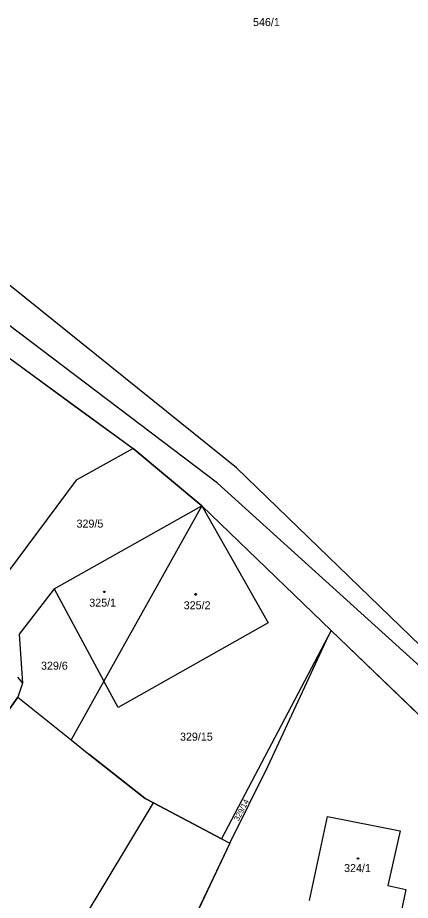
# Model space of a CAD drawing. Extents: x -634640 to -629202, y -1196156 to -1190068.
# Drawn here: x -632304.1 to -632220.7, y -1192469.9 to -1192282.4 of the extents above; entities that cross this region are included whole.
import ezdxf

# ---------------------------------------------------------------- set-up
doc = ezdxf.new("R2010")
doc.units = 0
for name, color, linetype in [('Obvod převzatý', 7, 'Continuous'), ('Obvod šetřený', 7, 'Continuous'), ('Vrstva 1', 7, 'Continuous'), ('Vrstva 2', 7, 'Continuous'), ('Vrstva 5', 7, 'Continuous')]:
    doc.layers.add(name, color=color, linetype=linetype)

msp = doc.modelspace()

# ---------------------------------------------------------------- linework, layer by layer
at = {"layer": 'Obvod převzatý'}
for points in [[(-632163.67, -1192480.89), (-632170.84, -1192475.395), (-632178.01, -1192469.9), (-632207.785, -1192441.235), (-632237.56, -1192412.57), (-632251.305, -1192399.34), (-632265.05, -1192386.11), (-632272.32, -1192380.04), (-632279.59, -1192373.97)], [(-632304.09, -1192426.76), (-632292.79, -1192435.85), (-632289.05, -1192438.85)], [(-632260.85, -1192456.84), (-632268.06, -1192453.015), (-632275.27, -1192449.19), (-632277.03, -1192448.26), (-632283.04, -1192443.555), (-632289.05, -1192438.85)], [(-632260.85, -1192456.84), (-632259.09, -1192457.78), (-632267.47, -1192475.48), (-632270.585, -1192482.88), (-632273.7, -1192490.28), (-632274.595, -1192496.04), (-632275.49, -1192501.8)]]:
    msp.add_lwpolyline(points, dxfattribs=at)
at = {"layer": 'Obvod šetřený'}
for points in [[(-632350.27, -1192322.41), (-632342.065, -1192328.395), (-632333.86, -1192334.38), (-632319.09, -1192345.155), (-632304.32, -1192355.93), (-632291.955, -1192364.95), (-632279.59, -1192373.97)], [(-632304.09, -1192426.76), (-632313.05, -1192439.46), (-632343.995, -1192483.305), (-632365.98, -1192514.45), (-632389.31, -1192496.99), (-632397.68, -1192490.725), (-632406.05, -1192484.46), (-632412.575, -1192479.78), (-632419.1, -1192475.1), (-632434.11, -1192464.33), (-632449.12, -1192453.56)]]:
    msp.add_lwpolyline(points, dxfattribs=at)
at = {"layer": 'Vrstva 1'}
for p, q in [((-632257.63, -1192378.06), (-632341.56, -1192310.6)), ((-632261.68, -1192381.3), (-632350.96, -1192313.7)), ((-632304.32, -1192355.93), (-632279.59, -1192373.97)), ((-632279.59, -1192373.97), (-632291.71, -1192380.67)), ((-632279.59, -1192373.97), (-632265.05, -1192386.11)), ((-632257.63, -1192378.06), (-632210.25, -1192423.94)), ((-632291.71, -1192380.67), (-632314.41, -1192411.03)), ((-632212.16, -1192426.15), (-632261.68, -1192381.3)), ((-632296.4, -1192403.77), (-632265.05, -1192386.11)), ((-632265.05, -1192386.11), (-632285.81, -1192423.33)), ((-632265.05, -1192386.11), (-632250.92, -1192410.95)), ((-632265.05, -1192386.11), (-632237.56, -1192412.57)), ((-632296.4, -1192403.77), (-632303.83, -1192413.41)), ((-632296.4, -1192403.77), (-632285.81, -1192423.33)), ((-632250.92, -1192410.95), (-632282.76, -1192428.94)), ((-632303.83, -1192413.41), (-632303.1, -1192423.75)), ((-632237.56, -1192412.57), (-632260.85, -1192456.84)), ((-632238.6, -1192414.81), (-632237.56, -1192412.57)), ((-632237.56, -1192412.57), (-632178.01, -1192469.9)), ((-632250.91, -1192441.37), (-632238.6, -1192414.81)), ((-632304.17, -1192422.54), (-632303.1, -1192423.75)), ((-632303.1, -1192423.75), (-632304.09, -1192426.76)), ((-632285.81, -1192423.33), (-632292.79, -1192435.85)), ((-632282.76, -1192428.94), (-632285.81, -1192423.33)), ((-632322.01, -1192452.16), (-632304.09, -1192426.76)), ((-632304.09, -1192426.76), (-632292.79, -1192435.85)), ((-632292.79, -1192435.85), (-632289.05, -1192438.85)), ((-632289.05, -1192438.85), (-632277.03, -1192448.26)), ((-632259.09, -1192457.78), (-632250.91, -1192441.37)), ((-632401.22, -1192658.24), (-632275.27, -1192449.19)), ((-632277.03, -1192448.26), (-632275.27, -1192449.19)), ((-632275.27, -1192449.19), (-632260.85, -1192456.84)), ((-632242.12, -1192469.91), (-632238.34, -1192452.1)), ((-632238.34, -1192452.1), (-632222.93, -1192455.17)), ((-632260.85, -1192456.84), (-632259.09, -1192457.78)), ((-632222.93, -1192455.17), (-632225.55, -1192466.75)), ((-632259.09, -1192457.78), (-632267.47, -1192475.48)), ((-632225.55, -1192466.75), (-632221.69, -1192467.63)), ((-632221.69, -1192467.63), (-632222.06, -1192469.33)), ((-632222.06, -1192469.33), (-632223.07, -1192474.02))]:
    msp.add_line(p, q, dxfattribs=at)
at = {"layer": 'Vrstva 5'}
for points in [[(-632285.65, -1192404.22), (-632285.56, -1192404.37), (-632285.65, -1192404.52), (-632285.83, -1192404.52), (-632285.92, -1192404.37), (-632285.83, -1192404.22), (-632285.65, -1192404.22)], [(-632266.23, -1192404.77), (-632266.14, -1192404.92), (-632266.23, -1192405.07), (-632266.41, -1192405.07), (-632266.5, -1192404.92), (-632266.41, -1192404.77), (-632266.23, -1192404.77)], [(-632231.75, -1192460.86), (-632231.66, -1192461.01), (-632231.75, -1192461.16), (-632231.93, -1192461.16), (-632232.02, -1192461.01), (-632231.93, -1192460.86), (-632231.75, -1192460.86)]]:
    msp.add_lwpolyline(points, dxfattribs=at)

# ---------------------------------------------------------------- texts
at = {"layer": 'Vrstva 2'}
for s, p in [('546/1', (-632254.153, -1192284.24)), ('329/5', (-632291.623, -1192390.75)), ('325/1', (-632288.923, -1192407.54)), ('325/2', (-632268.863, -1192408.09)), ('329/6', (-632299.173, -1192420.92)), ('329/15', (-632269.653, -1192436)), ('324/1', (-632234.813, -1192463.9))]:
    msp.add_text(s, height=1.7, dxfattribs=at).set_placement(p)
msp.add_text('329/14', height=1.2, rotation=62.50969, dxfattribs=at).set_placement((-632257.213, -1192453.191))

doc.saveas('drawing.dxf')
